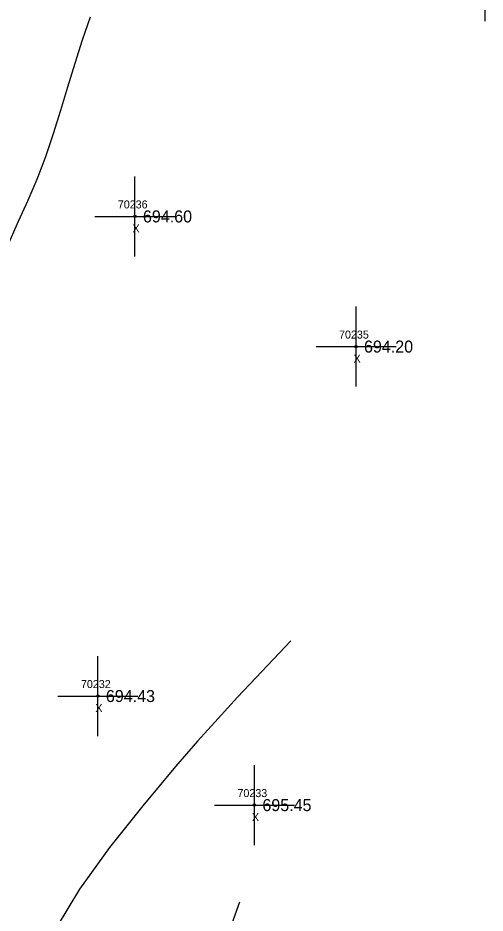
# Model space of a CAD drawing. Extents: x 1376587 to 1378239, y 1000335 to 1003031.
# Drawn here: x 1377617.7 to 1377676.1, y 1001837.8 to 1001949.7 of the extents above; entities that cross this region are included whole.
import ezdxf

# ---------------------------------------------------------------- set-up
doc = ezdxf.new("R2010")
doc.units = 0
for name, color, linetype in [('RD_DTM_Major1', 7, 'Continuous'), ('RD_DTM_Minor1', 7, 'Continuous'), ('RD_EX_Misc', 7, 'Continuous'), ('RD_EX_Misc_txCode', 7, 'Continuous'), ('RD_EX_TX_Misc_ELEV', 7, 'Continuous'), ('RD_SMD_Locator', 7, 'Continuous')]:
    doc.layers.add(name, color=color, linetype=linetype)

msp = doc.modelspace()

# ---------------------------------------------------------------- linework, layer by layer
at = {"layer": 'RD_DTM_Major1'}
msp.add_lwpolyline([(1377651.83, 1001871.85), (1377649.65, 1001869.58), (1377647.44, 1001867.25), (1377645.15, 1001864.8), (1377642.74, 1001862.17), (1377640.18, 1001859.3), (1377637.43, 1001856.14), (1377633.32, 1001851.24), (1377629.18, 1001846.01), (1377625.43, 1001840.8), (1377622.5, 1001835.98)], dxfattribs=at)
at = {"layer": 'RD_DTM_Minor1'}
for points in [[(1377616.64, 1001921.65), (1377617.8, 1001924.31), (1377618.99, 1001926.93), (1377620.12, 1001929.58), (1377621.19, 1001932.4), (1377622.17, 1001935.28), (1377623.08, 1001938.19), (1377623.97, 1001941.12), (1377624.87, 1001944.06), (1377625.81, 1001946.99), (1377626.81, 1001949.85)], [(1377645.43, 1001839.18), (1377641.62, 1001828.61)]]:
    msp.add_lwpolyline(points, dxfattribs=at)
at = {"layer": 'RD_EX_Misc'}
for p, q in [((1377676.11, 1001949.32), (1377676.11, 1001959.32)), ((1377632.35, 1001919.91), (1377632.35, 1001929.91)), ((1377627.35, 1001924.91), (1377637.35, 1001924.91)), ((1377659.98, 1001903.64), (1377659.98, 1001913.64)), ((1377654.98, 1001908.64), (1377664.98, 1001908.64)), ((1377627.72, 1001859.96), (1377627.72, 1001869.96)), ((1377622.72, 1001864.96), (1377632.72, 1001864.96)), ((1377647.28, 1001846.33), (1377647.28, 1001856.33)), ((1377642.28, 1001851.33), (1377652.28, 1001851.33))]:
    msp.add_line(p, q, dxfattribs=at)
at = {"layer": 'RD_SMD_Locator'}
for centre in [(1377632.35, 1001924.91), (1377659.98, 1001908.64), (1377627.72, 1001864.96), (1377647.28, 1001851.33)]:
    msp.add_circle(centre, 0.15, dxfattribs=at)

# ---------------------------------------------------------------- texts
at = {"layer": 'RD_EX_Misc_txCode'}
for s, p in [('70236', (1377630.21, 1001925.91)), ('X', (1377632.04, 1001922.91)), ('70235', (1377657.86, 1001909.64)), ('X', (1377659.67, 1001906.64)), ('70232', (1377625.6, 1001865.96)), ('X', (1377627.4, 1001862.96)), ('70233', (1377645.16, 1001852.33)), ('X', (1377646.97, 1001849.33))]:
    msp.add_text(s, height=1, dxfattribs=at).set_placement(p)
at = {"layer": 'RD_EX_TX_Misc_ELEV'}
for s, p in [('694.60', (1377633.35, 1001924.16)), ('694.20', (1377660.98, 1001907.89)), ('694.43', (1377628.72, 1001864.21)), ('695.45', (1377648.28, 1001850.58))]:
    msp.add_text(s, height=1.5, dxfattribs=at).set_placement(p)

doc.saveas('drawing.dxf')
